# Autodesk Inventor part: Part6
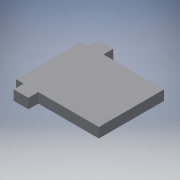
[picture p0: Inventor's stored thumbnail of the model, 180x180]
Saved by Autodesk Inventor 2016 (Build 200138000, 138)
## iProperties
Created: 2017-06
Part Number: Part6
Material: Generic
Document SubType Name: Modeling
Designer: laboratorioesan
Density: 1 g/cm^3
Appearance: Default
Author: laboratorioesan
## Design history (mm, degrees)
sketch "Sketch1"
  geometry: L1 (0, 0)-(-4, 0) reference; L2 (0, 0)-(0, 3) reference; L3 (-4, 3)-(0, 3) reference; L4 (-4, 0)-(-4, 3) reference; L5 (-4, 25.65)-(0, 25.65) reference; L6 (-4, 25.65)-(-4, 22.65) reference; L7 (0, 22.65)-(-4, 22.65) reference; L8 (0, 25.65)-(0, 22.65) reference; L9 (-6.553, 22.65)-(-6.553, 3) reference; L10 (15.325, 0)-(15.325, 3) reference; L11 (15.325, 25.65)-(15.325, 22.65) reference; L12 (-6.553, 3)-(18.447, 3); L13 (18.447, 3)-(18.447, 22.65); L14 (18.447, 22.65)-(-6.553, 22.65); L15 (-6.553, 22.65)-(-6.553, 3); L16 (-4.2, 3)-(-4.2, 0); L17 (-4.2, 0)-(0.2, 0); L18 (0.2, 0)-(0.2, 3); L19 (-4.2, 22.65)-(-4.2, 25.65); L20 (-4.2, 25.65)-(0.2, 25.65); L21 (0.2, 25.65)-(0.2, 22.65)
  constraints: 20 end point, 7 point on line, 3 perpendicular, 2 horizontal, 2 parallel, 2 vertical alignment, 1 vertical
  dimensions: "d0" = 25 distance of L14.end L13.end; "d1" = 0.2 horizontal distance of L7.start L20.end; "d2" = 0.2 distance of L19.start L6.end
extrude "Extrusion1" new body sketch "Sketch1" distance "d3" = 3; taper "d4" = 0 deg
body "Solid1"
node "Reference1"
node "Reference2"
node "Reference3"
node "Reference4"
node "Reference5"
